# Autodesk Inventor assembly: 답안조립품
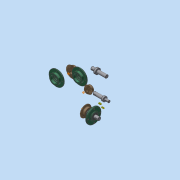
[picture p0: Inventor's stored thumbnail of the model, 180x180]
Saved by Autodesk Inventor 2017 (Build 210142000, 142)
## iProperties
Part Number: 답안조립품
Material: 일반
Document SubType Name: Assembly
Designer: MRC
Author: MRC
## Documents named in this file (16)
- C:\Users\MRC\Desktop\710116V1005\답안조립품.iam
- C:\Users\MRC\Desktop\710116V1005\메인 베벨기어.ipt
- C:\Users\MRC\Desktop\710116V1005\메인 축.ipt
- 메인 축.ipt
- C:\Users\MRC\Desktop\710116V1005\베어링 6203.ipt
- C:\Users\MRC\Desktop\710116V1005\본체.ipt
- C:\Users\MRC\Desktop\710116V1005\볼트 M4.ipt
- 볼트 M4.ipt
- C:\Users\MRC\Desktop\710116V1005\서브 베벨기어.ipt
- C:\Users\MRC\Desktop\710116V1005\서브 축.ipt
- 서브 축.ipt
- C:\Users\MRC\Desktop\710116V1005\오일 실.ipt
- 오일 실.ipt
- C:\Users\MRC\Desktop\710116V1005\커버.ipt
- C:\Users\MRC\Desktop\710116V1005\키 4x4.ipt
- C:\Users\MRC\Desktop\710116V1005\키 5x5.ipt
